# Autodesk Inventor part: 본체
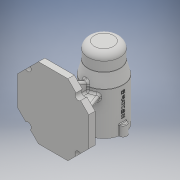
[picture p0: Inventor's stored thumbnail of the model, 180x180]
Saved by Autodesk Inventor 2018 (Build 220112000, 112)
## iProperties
Created: 2019-12
Part Number: 본체
Material: Generic
Document SubType Name: Modeling
Designer: Administrator
Density: 1 g/cm^3
Appearance: Default
Author: Administrator
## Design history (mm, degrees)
sketch "스케치1"
  geometry: L1 (-23.196, -56)-(-56, -23.196); L2 (-56, -23.196)-(-56, 23.196); L3 (-56, 23.196)-(-23.196, 56); L4 (-23.196, 56)-(23.196, 56); L5 (23.196, 56)-(56, 23.196); L6 (56, 23.196)-(56, -23.196); L7 (56, -23.196)-(23.196, -56); L8 (23.196, -56)-(-23.196, -56); 2 further points
  constraints: 16 end point, 1 coincident, 1 horizontal, 17 other
  dimensions: "d0" = 112 distance between parallel lines of L2 L6
extrude "돌출1" new body sketch "스케치1" distance "d1" = 10; taper "d2" = 0 deg
sketch "스케치2"
  geometry: L1 (0, 0)-(10, 0); L2 (10, -23.196)-(10, -56) reference; L3 (80, -56)-(110, -56); L4 (110, -56)-(110, 11); L5 (110, 11)-(80, 11); L6 (80, 11)-(80, -56); L7 (80, 11)-(110, 11); L8 (105, 31)-(80, 31); L9 (80, 31)-(80, 11); L10 (80, 31)-(105, 31); L11 (105, 31)-(105, 56); L12 (105, 56)-(80, 56); L13 (80, 56)-(80, 31); L14 (105, 31)-(110, 11)
  constraints: 26 end point, 5 parallel, 4 horizontal, 2 perpendicular, 2 point on line
  dimensions: "d5" = 112 distance between parallel lines of L3 L12; "d6" = 60 diameter of L4 L6; "d7" = 50 diameter of L11 L13; "d8" = 25 distance between parallel lines of L8 L12; "d9" = 45 distance between parallel lines of L5 L12
revolve "회전1" sketch "스케치2" stored, may be unused: angle "d10" = 90 deg
sketch "스케치3"
  geometry: L1 (5.391, 38)-(60.901, 12.115); L2 (60.901, 12.115)-(60.901, -31); L3 (10, 23.196)-(10, 56) reference; L4 (60.901, -31)-(5.391, -31); L5 (5.391, -31)-(5.391, 38); L6 (0, -56)-(10, -56) reference; L7 (0, 56)-(10, 56) reference; 1 further point
  constraints: 8 end point, 2 perpendicular, 1 parallel
  dimensions: "d11" = 115 deg angle of L3 L1; "d12" = 25 distance between parallel lines of L4 L6; "d13" = 18 distance from line of L1.start L7
extrude "돌출2" join sketch "스케치3" stored distance "d14" = 8; taper "d15" = 0 deg
sketch "스케치4"
  geometry: L1 (36, 5.894)-(16.107, 60.549); L2 (16.107, 60.549)-(-16.107, 60.549); L3 (23.196, 10)-(56, 10) reference; L4 (-16.107, 60.549)-(-36, 5.894); L5 (-36, 5.894)-(36, 5.894); L6 (-56, 10)-(-23.196, 10) reference; L7 (56, 0)-(56, 10) reference; L8 (-56, 0)-(-56, 10) reference; 1 further point
  constraints: 8 end point, 2 parallel
  dimensions: "d16" = 110 deg angle of L6 L4; "d17" = 110 deg angle of L3 L1; "d18" = 20 distance from line of L1.start L7; "d19" = 20 distance from line of L4.end L8
extrude "돌출3" join sketch "스케치4" stored distance "d20" = 8; taper "d21" = 0 deg
sketch "스케치5"
  geometry: L1 (55, 56)-(105, 56) reference; L2 (50, -56)-(110, -56) reference; L3 (80, -56)-(101, -56); L4 (101, -56)-(101, -41); L5 (101, -41)-(80, -41); L6 (80, -41)-(80, -56); L7 (80, -41)-(101, -41); L8 (104, -38)-(104, 10); L9 (101, 13)-(80, 13); L10 (80, 13)-(80, -41); L11 (80, 13)-(101, 13); L12 (101, 13)-(101, 24.7); L13 (100.7, 25)-(80, 25); L14 (80, 25)-(80, 13); L15 (80, 25)-(97.5, 25); L16 (97.5, 25)-(97.5, 42.7); L17 (97.2, 43)-(80, 43); L18 (80, 43)-(80, 25); L19 (80, 43)-(96, 43); L20 (96, 43)-(96, 46.7); L21 (95.7, 47)-(80, 47); L22 (80, 47)-(80, 43); L23 (80, 47)-(90.5, 47); L24 (90.5, 47)-(90.5, 47); L25 (87.5, 50)-(80, 50); L26 (80, 50)-(80, 47); A1 r 3 centre (87.5, 47) between (90.5, 47) and (87.5, 50); A2 r 0.3 centre (95.7, 46.7) between (96, 46.7) and (95.7, 47); A3 r 0.3 centre (97.2, 42.7) between (97.5, 42.7) and (97.2, 43); A4 r 0.3 centre (100.7, 24.7) between (101, 24.7) and (100.7, 25); A5 r 3 centre (101, 10) between (104, 10) and (101, 13); A6 r 3 centre (101, -38) between (101, -41) and (104, -38); 4 further points
  constraints: 48 end point, 12 parallel, 12 point on circle, 12 tangent, 7 point on line, 6 centre point, 6 horizontal, 6 perpendicular, 3 equal radius, 1 midpoint
  dimensions: "d22" = 15 distance between parallel lines of L2 L5; "d23" = 54 distance between parallel lines of L5 L11; "d24" = 12 distance between parallel lines of L11 L13; "d25" = 18 distance between parallel lines of L15 L17; "d26" = 4 distance between parallel lines of L17 L21; "d27" = 3 distance between parallel lines of L21 L25; "d28" = 42 diameter of L4 L6; "d29" = 48 diameter of L8 L10; "d30" = 35 diameter of L16 L18; "d31" = 32 diameter of L20 L22; "d32" = 21 diameter of L24 L26; "d33" = 3 radius of A1; "d34" = 0.3 radius of A2; "d58" = 3 radius of A5 (derived)
revolve "회전2" sketch "스케치5" stored, may be unused: angle "d35" = 90 deg
sketch "스케치6"
  geometry: C1 r 6 at (0, 30); 2 further points
  constraints: 1 centre point, 1 vertical alignment, 1 other
  dimensions: "d36" = 12 diameter of C1
extrude "돌출4" join sketch "스케치6" distance "d37" = 16; taper "d38" = 0 deg
fillet "모깎기1" dims "d39" = 1
sketch "스케치7"
  geometry: C1 r 10.5 at (0, -30) reference; A1 r 30 centre (0, -30) between (0, 0) and (30, -30); 3 further points
  constraints: 4 point on circle, 1 centre point, 1 coincident
  dimensions: "d43" = 60 diameter of A1
hole "구멍1" sketch "스케치7" at (0, 0), (30, -30), (-30, -30) diameter "d44" = 3.242; stored, may be unused: countersink angle "d48" = 90 deg, drill point angle "d50" = 118 deg; dims "d45" = 8, "d46" = 4, "d47" = 2, "d49" = 11
sketch "스케치8"
  geometry: L1 (-56, 23.196)-(-23.196, 56) reference; L2 (23.196, 56)-(56, 23.196) reference; L3 (39.598, 39.598)-(-39.598, -39.598); L4 (-23.196, -56)-(-56, -23.196) reference; L5 (-39.598, 39.598)-(39.598, -39.598); L6 (56, -23.196)-(23.196, -56) reference; C1 r 5 at (39.598, -39.598); C2 r 5 at (39.598, 39.598); C3 r 5 at (-39.598, 39.598); C4 r 5 at (-39.598, -39.598); 1 further point
  constraints: 4 centre point, 4 coincident, 4 end point, 4 midpoint
  dimensions: "d51" = 10 diameter of C1; "d52" = 10 diameter of C2; "d53" = 10 diameter of C3; "d54" = 10 diameter of C4
extrude "돌출5" cut sketch "스케치8" distance "d55" = 30; taper "d56" = 0 deg
fillet "모깎기2" dims "d57" = 10
chamfer "모따기1" distance "d59" = 1; stored, may be unused: second distance "d60" = 2, angle "d61" = 45 deg
fillet "모깎기3" dims "d62" = 3
fillet "모깎기4" dims "d63" = 3
node "작업 평면1"
sketch "스케치9"
  geometry: L1 (-22, -33.5)-(22, -33.5) reference; 3 further points
  constraints: 1 midpoint, 1 other
  dimensions: "d64" = 0 horizontal distance of point (0, -33.5) point (0, 7.5); "d65" = 41 distance from line of L1 point (0, 7.5)
feature "엠보싱1" sketch "스케치9" dims "d0" = 112, "d6" = 60, "d66" = 0.5, "d67" = 0
hole "구멍2" diameter "d70" = 3.242; stored, may be unused: countersink angle "d74" = 90 deg, drill point angle "d76" = 118 deg; dims "d68" = 10, "d69" = 10, "d71" = 8, "d72" = 4, "d73" = 2, "d75" = 11
node "솔리드1"
pattern_circular "원형 패턴1" dims angle "d41" = 360 deg
